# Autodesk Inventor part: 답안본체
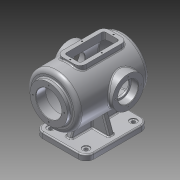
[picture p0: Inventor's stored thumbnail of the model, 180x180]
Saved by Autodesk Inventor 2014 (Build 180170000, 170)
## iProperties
Created: 2021-11
Part Number: 답안본체
Material: 알루미늄 6061
Document SubType Name: Modeling
Designer: kb542-12
Density: 2.71 g/cm^3
Appearance: 알루미늄 - 평지
Mass: 3554.29 g
Surface Area: 2405.16 cm^2
Volume: 1311.55 cm^3
Author: kb542-12
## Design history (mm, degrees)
sketch "스케치1"
  geometry: L1 (0, 0)-(210, 0); L2 (10, 65)-(10, 47.5); L3 (10, 47.5)-(0, 47.5); L4 (25, 55)-(25, 32.5); L5 (25, 32.5)-(0, 32.5); L6 (0, 32.5)-(0, 47.5); L7 (10, 65)-(185.993, 65); L8 (25, 55)-(181.239, 55); A1 r 100 centre (110, 0) between (210, 0) and (185.993, 65); A2 r 90 centre (110, 0) between (200, 0) and (181.239, 55)
  constraints: 16 end point, 4 point on circle, 3 perpendicular, 2 centre point, 2 point on line, 2 vertical alignment, 1 horizontal, 1 parallel, 1 vertical
  dimensions: "d0" = 210 distance of L1.start L1.end; "d6" = 65 diameter of L5 L1; "d7" = 95 diameter of L3 L1; "d8" = 25 distance of L4.end L5.end; "d9" = 10 distance between parallel lines of L6 L2; "d15" = 100 radius of A1; "d18" = 130 diameter of L7 L1; "d20" = 10 radial gap between concentric circles of A1 A2; "d23" = 110 diameter of L8 L1
revolve "회전1" sketch "스케치1" stored, may be unused: angle "d24" = 90 deg
node "작업 평면1"
sketch "스케치2"
  geometry: L1 (65, 30)-(155, 30); L2 (170, 15)-(170, -15); L3 (155, -30)-(65, -30); L4 (50, -15)-(50, 15); L5 (155, 20)-(65, 20); L6 (60, 15)-(60, -15); L7 (65, -20)-(155, -20); L8 (160, -15)-(160, 15); L9 (55, 25)-(165, 25); L10 (165, 25)-(165, -25); L11 (165, -25)-(55, -25); L12 (55, -25)-(55, 25); A1 r 15 centre (65, 15) between (65, 30) and (50, 15); A2 r 15 centre (155, 15) between (170, 15) and (155, 30); A3 r 15 centre (155, -15) between (155, -30) and (170, -15); A4 r 15 centre (65, -15) between (50, -15) and (65, -30); A5 r 5 centre (65, 15) between (65, 20) and (60, 15); A6 r 5 centre (65, -15) between (60, -15) and (65, -20); A7 r 5 centre (155, -15) between (155, -20) and (160, -15); A8 r 5 centre (155, 15) between (160, 15) and (155, 20); 14 further points
  constraints: 24 end point, 16 point on circle, 10 midpoint, 8 centre point, 8 tangent, 6 parallel, 6 point on line, 4 coincident, 3 equal radius, 3 horizontal alignment, 3 perpendicular, 2 horizontal, 7 other
  dimensions: "d26" = 120 distance of point (50, 30) point (170, 30); "d27" = 60 distance of point (50, -30) point (50, 30); "d28" = 50 distance from line of point (0, 0) L4; "d29" = 15 radius of A1; "d30" = 10 distance between parallel lines of L1 L5; "d31" = 50 distance of point (110, -25) point (110, 25); "d32" = 110 distance of point (165, 0) point (55, 0); "d33" = 5 distance of point (50, 0) point (55, 0)
extrude "돌출1" join sketch "스케치2" stored distance "d34" = 10; taper "d35" = 0 deg
hole "구멍1" sketch "스케치2" diameter "d36" = 3.242; stored, may be unused: countersink angle "d40" = 90 deg, drill point angle "d42" = 118 deg; dims "d37" = 9, "d38" = 4, "d39" = 2, "d41" = 11
node "작업 평면2"
sketch "스케치3"
  geometry: C1 r 40 at (127, 0); 1 further point
  constraints: 1 centre point, 1 horizontal alignment
  dimensions: "d44" = 80 diameter of C1; "d45" = 127 distance of point (0, 0) C1.centre
extrude "돌출2" join sketch "스케치3" stored distance "d46" = 10; taper "d47" = 0 deg
hole "구멍2" diameter "d50" = 42; stored, may be unused: countersink angle "d54" = 90 deg, drill point angle "d56" = 118 deg; dims "d48" = 10, "d49" = 10, "d51" = 9, "d52" = 52, "d53" = 18, "d55" = 11
sketch "스케치4"
  geometry: C1 r 40 at (127, 0) reference; A1 r 32.5 centre (127, 0) between (127, 32.5) and (127, -32.5); 3 further points
  constraints: 4 point on circle, 2 horizontal alignment, 2 vertical alignment, 1 centre point, 1 concentric
  dimensions: "d57" = 65 diameter of A1
hole "구멍3" sketch "스케치4" at (127, 32.5), (127, -32.5), (94.5, 0), (159.5, 0) diameter "d58" = 3.242; stored, may be unused: countersink angle "d62" = 90 deg, drill point angle "d64" = 118 deg; dims "d59" = 11, "d60" = 52, "d61" = 18, "d63" = 13
extrude "돌출3" cut sketch "스케치2" stored distance "d65" = 10; taper "d66" = 0 deg
node "작업 평면3"
sketch "스케치5"
  geometry: L1 (-170, 65)-(-50, 65); L2 (-30, 45)-(-30, -45); L3 (-50, -65)-(-170, -65); L4 (-190, -45)-(-190, 45); C1 r 4.5 at (-170, 45); C2 r 4.5 at (-50, 45); C3 r 4.5 at (-170, -45); C4 r 4.5 at (-50, -45); A1 r 20 centre (-170, 45) between (-170, 65) and (-190, 45); A2 r 20 centre (-50, 45) between (-30, 45) and (-50, 65); A3 r 20 centre (-50, -45) between (-50, -65) and (-30, -45); A4 r 20 centre (-170, -45) between (-190, -45) and (-170, -65); 5 further points
  constraints: 8 centre point, 8 end point, 8 point on circle, 8 tangent, 6 equal radius, 6 point on line, 4 coincident, 2 parallel, 1 horizontal, 1 horizontal alignment, 1 midpoint, 1 perpendicular
  dimensions: "d68" = 160 distance of point (-190, 65) point (-30, 65); "d69" = 130 distance of point (-30, 65) point (-30, -65); "d70" = 30 distance from line of point (0, 0) L2; "d71" = 20 radius of A1; "d72" = 9 diameter of C1
extrude "돌출5" join sketch "스케치5" distance "d75" = 14; taper "d76" = 0 deg
sketch "스케치7"
  geometry: A1 r 20 centre (50, 45) between (50, 65) and (30, 45) reference; A2 r 20 centre (50, -45) between (30, -45) and (50, -65) reference; A3 r 20 centre (170, -45) between (170, -65) and (190, -45) reference; A4 r 20 centre (170, 45) between (190, 45) and (170, 65) reference; 5 further points
  constraints: 4 coincident
hole "구멍4" sketch "스케치7" at (50, 45), (170, 45), (170, -45), (50, -45) diameter "d82" = 18; stored, may be unused: countersink angle "d86" = 90 deg, drill point angle "d88" = 0 deg; dims "d83" = 11, "d84" = 52, "d85" = 18, "d87" = 2
node "작업 평면4"
sketch "스케치9"
  geometry: L1 (0, -14)-(90, -14) reference; L2 (78.809, -58.485)-(95, -14); L3 (-5, -14)-(11.191, -58.485); L4 (45, -14)-(45, -114); L5 (95, -14)-(-5, -14); L6 (99, -14)-(81, -14) reference; A1 r 65 centre (45, -114) between (78.809, -58.485) and (11.191, -58.485) reference; A2 r 65 centre (45, -114) between (78.809, -58.485) and (11.191, -58.485); 2 further points
  constraints: 8 end point, 4 point on circle, 2 point on line, 1 centre point, 1 collinear, 1 concentric, 1 midpoint, 1 perpendicular, 1 vertical alignment, 1 other
  dimensions: "d98" = 110 deg angle of L6 L2; "d99" = 100 distance of L3.start L2.end
extrude "돌출6" join sketch "스케치9" stored distance "d100" = 14; taper "d101" = 0 deg
sketch "스케치8"
  geometry: L1 (10, -65)-(10, 65) reference; L2 (185.993, -65)-(185.993, 65) reference; L3 (65, -57.663)-(155, -57.663) reference; L4 (170, -63.246)-(170, -63.246) reference; L5 (155, -57.663)-(65, -57.663) reference; L6 (50, -63.246)-(50, -63.246) reference; L7 (30, 114)-(30, 100) reference; L8 (0, -47.5)-(0, 47.5) reference; L9 (30, 100)-(50, 100) reference; L10 (170, 100)-(157.261, 65); L11 (181.239, 55)-(25, 55) reference; L12 (10, 65)-(185.993, 65) reference; L13 (50, 100)-(170, 100) reference; L14 (110, 100)-(110, 65); 3 further points
  constraints: 4 end point, 3 point on line, 1 midpoint, 1 perpendicular, 6 other
  dimensions: "d102" = 110 deg angle of L9 L10; "d104" = 60 distance from line of L14 L10.start (derived)
feature "리브1" sketch "스케치8" dims "d105" = 1, "d106" = 14, "d107" = 0, "d108" = 0, "d109" = 1, "d110" = 1
sketch "스케치10"
  geometry: C1 r 32.5 at (0, 0) reference; A1 r 40 centre (0, 0) between (0, 40) and (0, -40); 2 further points
  constraints: 4 point on circle, 2 horizontal alignment, 2 vertical alignment, 1 centre point, 1 coincident
  dimensions: "d111" = 80 diameter of A1
hole "구멍5" sketch "스케치10" at (0, 40), (0, -40), (-40, 0), (40, 0) diameter "d112" = 3.242; stored, may be unused: countersink angle "d116" = 90 deg, drill point angle "d118" = 0 deg; dims "d113" = 11, "d114" = 52, "d115" = 18, "d117" = 13
fillet "모깎기1" dims "d119" = 10
fillet "모깎기3" dims "d121" = 3
fillet "모깎기2" dims "d120" = 3
fillet "모깎기4" dims "d122" = 3
chamfer "모따기1" distance "d123" = 1; stored, may be unused: second distance "d124" = 2, angle "d125" = 45 deg
node "솔리드1"
mirror "대칭1"
mirror "대칭2"
node "투영된 루프1"
other parameters: "d43" = 75, "d67" = 114
